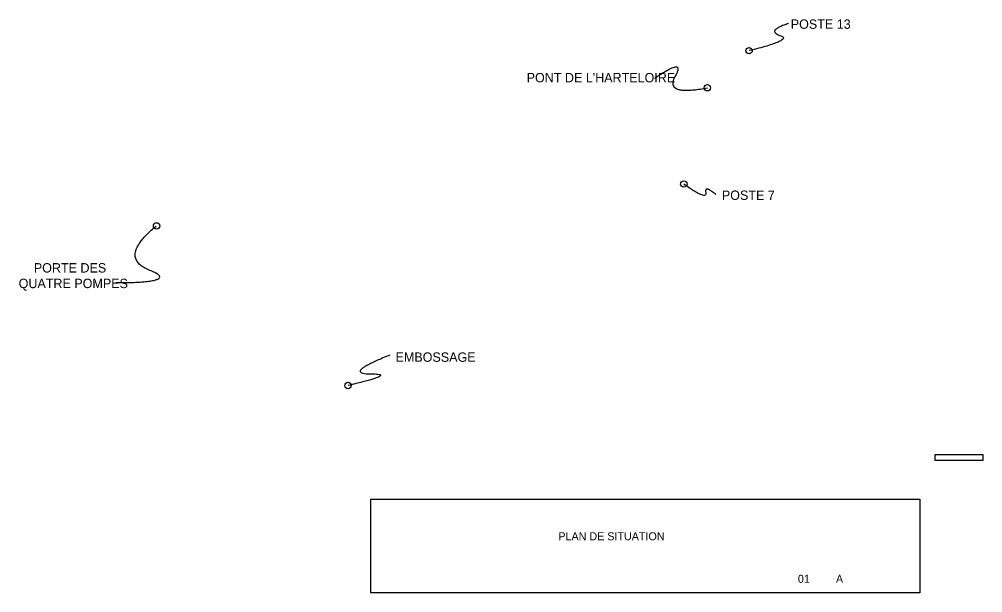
# Model space of a CAD drawing. Extents: x -170 to 10, y 3 to 110.
import ezdxf

# ---------------------------------------------------------------- set-up
doc = ezdxf.new("R2010")
doc.units = 0
doc.layers.add('Default', color=7, linetype='Continuous')
doc.layers.add('DH_CADRE-CARTOUCHE', color=7, linetype='Continuous')

msp = doc.modelspace()

# ---------------------------------------------------------------- linework, layer by layer
at = {"layer": 'Default'}
msp.add_lwpolyline([(0.8, 29.1), (9.71, 29.1), (9.71, 27.94), (0.8, 27.94)], close=True, dxfattribs=at)
at = {"layer": 'DH_CADRE-CARTOUCHE'}
msp.add_lwpolyline([(-104.55, 20.77), (-2.05, 20.77), (-2.05, 3.27), (-104.55, 3.27)], close=True, dxfattribs=at)
for centre in [(-33.93, 104.49), (-41.72, 97.56), (-46.11, 79.58), (-144.6, 71.76), (-108.83, 41.97)]:
    msp.add_circle(centre, 0.597, dxfattribs=at)
for points in [[(-26.54, 109.56), (-30.79, 108.19), (-25.52, 106.49), (-33.93, 104.49)], [(-51.52, 99.36), (-45.67, 103.39), (-49.84, 95.98), (-41.72, 97.56)], [(-40.09, 77.6), (-42.34, 79.5), (-41.68, 76.4), (-46.11, 79.58)], [(-152.21, 61.17), (-140.03, 61.17), (-151.82, 65.83), (-144.68, 71.73)], [(-101, 47.64), (-109.84, 44.14), (-99.37, 44.14), (-108.83, 41.97)]]:
    msp.add_open_spline(points, degree=2, dxfattribs=at)

# ---------------------------------------------------------------- texts
at = {"layer": 'Default'}
for s, p in [('PLAN DE SITUATION', (-69.55, 13.06)), ('01', (-24.81, 5.12)), ('A', (-17.7, 5.12))]:
    msp.add_text(s, height=1.5, dxfattribs=at).set_placement(p)
at = {"layer": 'DH_CADRE-CARTOUCHE'}
for s, height, p in [('POSTE 13', 1.75, (-26.14, 108.57)), ("PONT DE L'HARTELOIRE", 1.7496, (-75.47, 98.57)), ('POSTE 7', 1.75, (-39.01, 76.62)), ('PORTE DES', 1.75, (-167.52, 63.06)), ('QUATRE POMPES', 1.7496, (-170.35, 60.15)), ('EMBOSSAGE', 1.75, (-99.96, 46.39))]:
    msp.add_text(s, height=height, dxfattribs=at).set_placement(p)

doc.saveas('drawing.dxf')
